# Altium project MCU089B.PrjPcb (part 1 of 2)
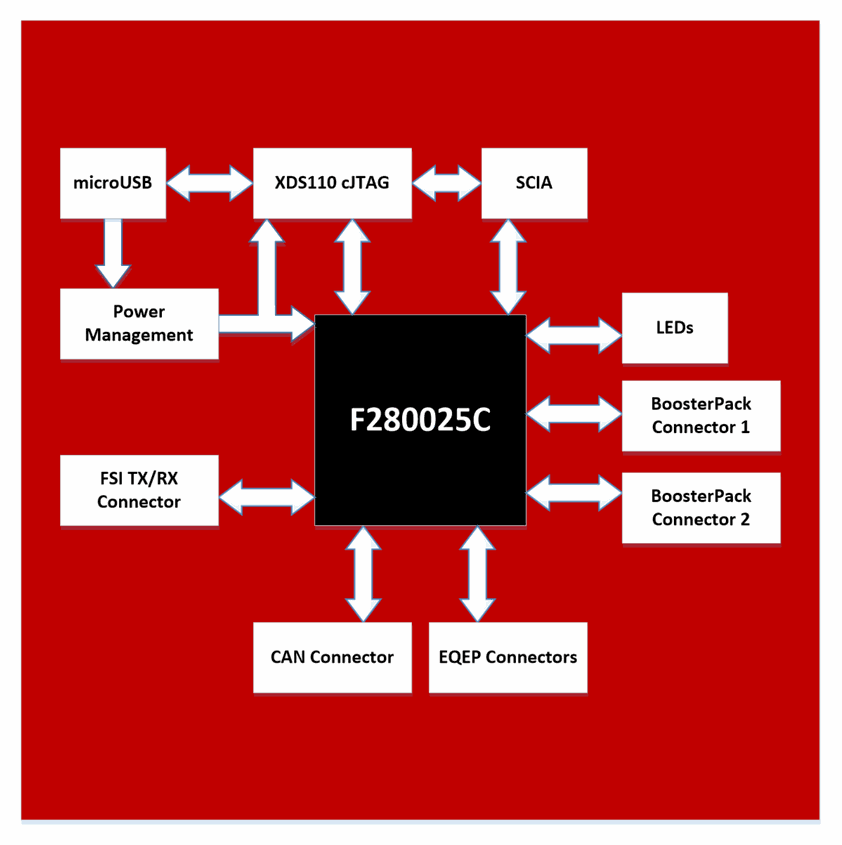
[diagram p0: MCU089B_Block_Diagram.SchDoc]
TID: N/A; TechSupport: http://www.ti.com/support; SCH_Rev: B; PRJ_Title: LAUNCHXL-F280025C; PRJ_Number: MCU089; PRJ_Engineer: Kevin Allen; PRJ_Customer: Public Release; PCB_Rev: B; PCB_Layout: a0232540; CopyrightYear: 2022
7 sheets, 262 parts. Net scope: global (net labels, ports and power ports of the same name join across sheets).
Board file: MCU089B.PcbDoc
Sheets:
  MCU089B_Block_Diagram.SchDoc
  MCU089B_Connectors.SchDoc
  MCU089B_AltRouting_Misc.SchDoc
  MCU089B_F280025C_Device.SchDoc
  MCU089B_XDS110_USB_Power.SchDoc
  MCU089B_XDS110_MCU.SchDoc
  MCU089B_Hardware.SchDoc

## Sheet MCU089B_Block_Diagram.SchDoc
size 431 x 279 mm; Date: Not shown in title block; ApprovedBy: Not shown in title block; CheckedBy: Not shown in title block; Author: Not shown in title block; CompanyName: Not shown in title block; Engineer: Not shown in title block; Organization: Not shown in title block; Address1: Not shown in title block; Address2: Not shown in title block; Address3: Not shown in title block; Address4: Not shown in title block; DocumentNumber: 1; Revision: Use project parameter SCH_Rev; SheetNumber: 1; SheetTotal: 8; PageSetup: Record=PageOptions¦CenterHorizontal=True¦CenterVertical=True¦PrintScale=1.00¦XCorrection=1.00¦YCorrection=1.00¦PrintKind=0¦BorderSize=5000000¦LeftOffset=0¦BottomOffset=0¦Orientation=2¦PaperLength=1000¦PaperWidth=1000¦Scale=100¦PaperSource=15¦PrintQuality=600¦MediaType=1¦DitherType=10¦PaperKind=Letter¦PrintScaleMode=1

## Sheet MCU089B_Connectors.SchDoc
size 431 x 279 mm; Date: Not shown in title block; ApprovedBy: Not shown in title block; CheckedBy: Not shown in title block; Author: Not shown in title block; CompanyName: Not shown in title block; Engineer: Not shown in title block; Organization: Not shown in title block; Address1: Not shown in title block; Address2: Not shown in title block; Address3: Not shown in title block; Address4: Not shown in title block; DocumentNumber: 2; Revision: Use project parameter SCH_Rev; SheetNumber: 2; SheetTotal: 8; PageSetup: Record=PageOptions¦CenterHorizontal=True¦CenterVertical=True¦PrintScale=1.00¦XCorrection=1.00¦YCorrection=1.00¦PrintKind=0¦BorderSize=5000000¦LeftOffset=0¦BottomOffset=0¦Orientation=2¦PaperLength=1000¦PaperWidth=1000¦Scale=100¦PaperSource=15¦PrintQuality=600¦MediaType=1¦DitherType=10¦PaperKind=Letter¦PrintScaleMode=1
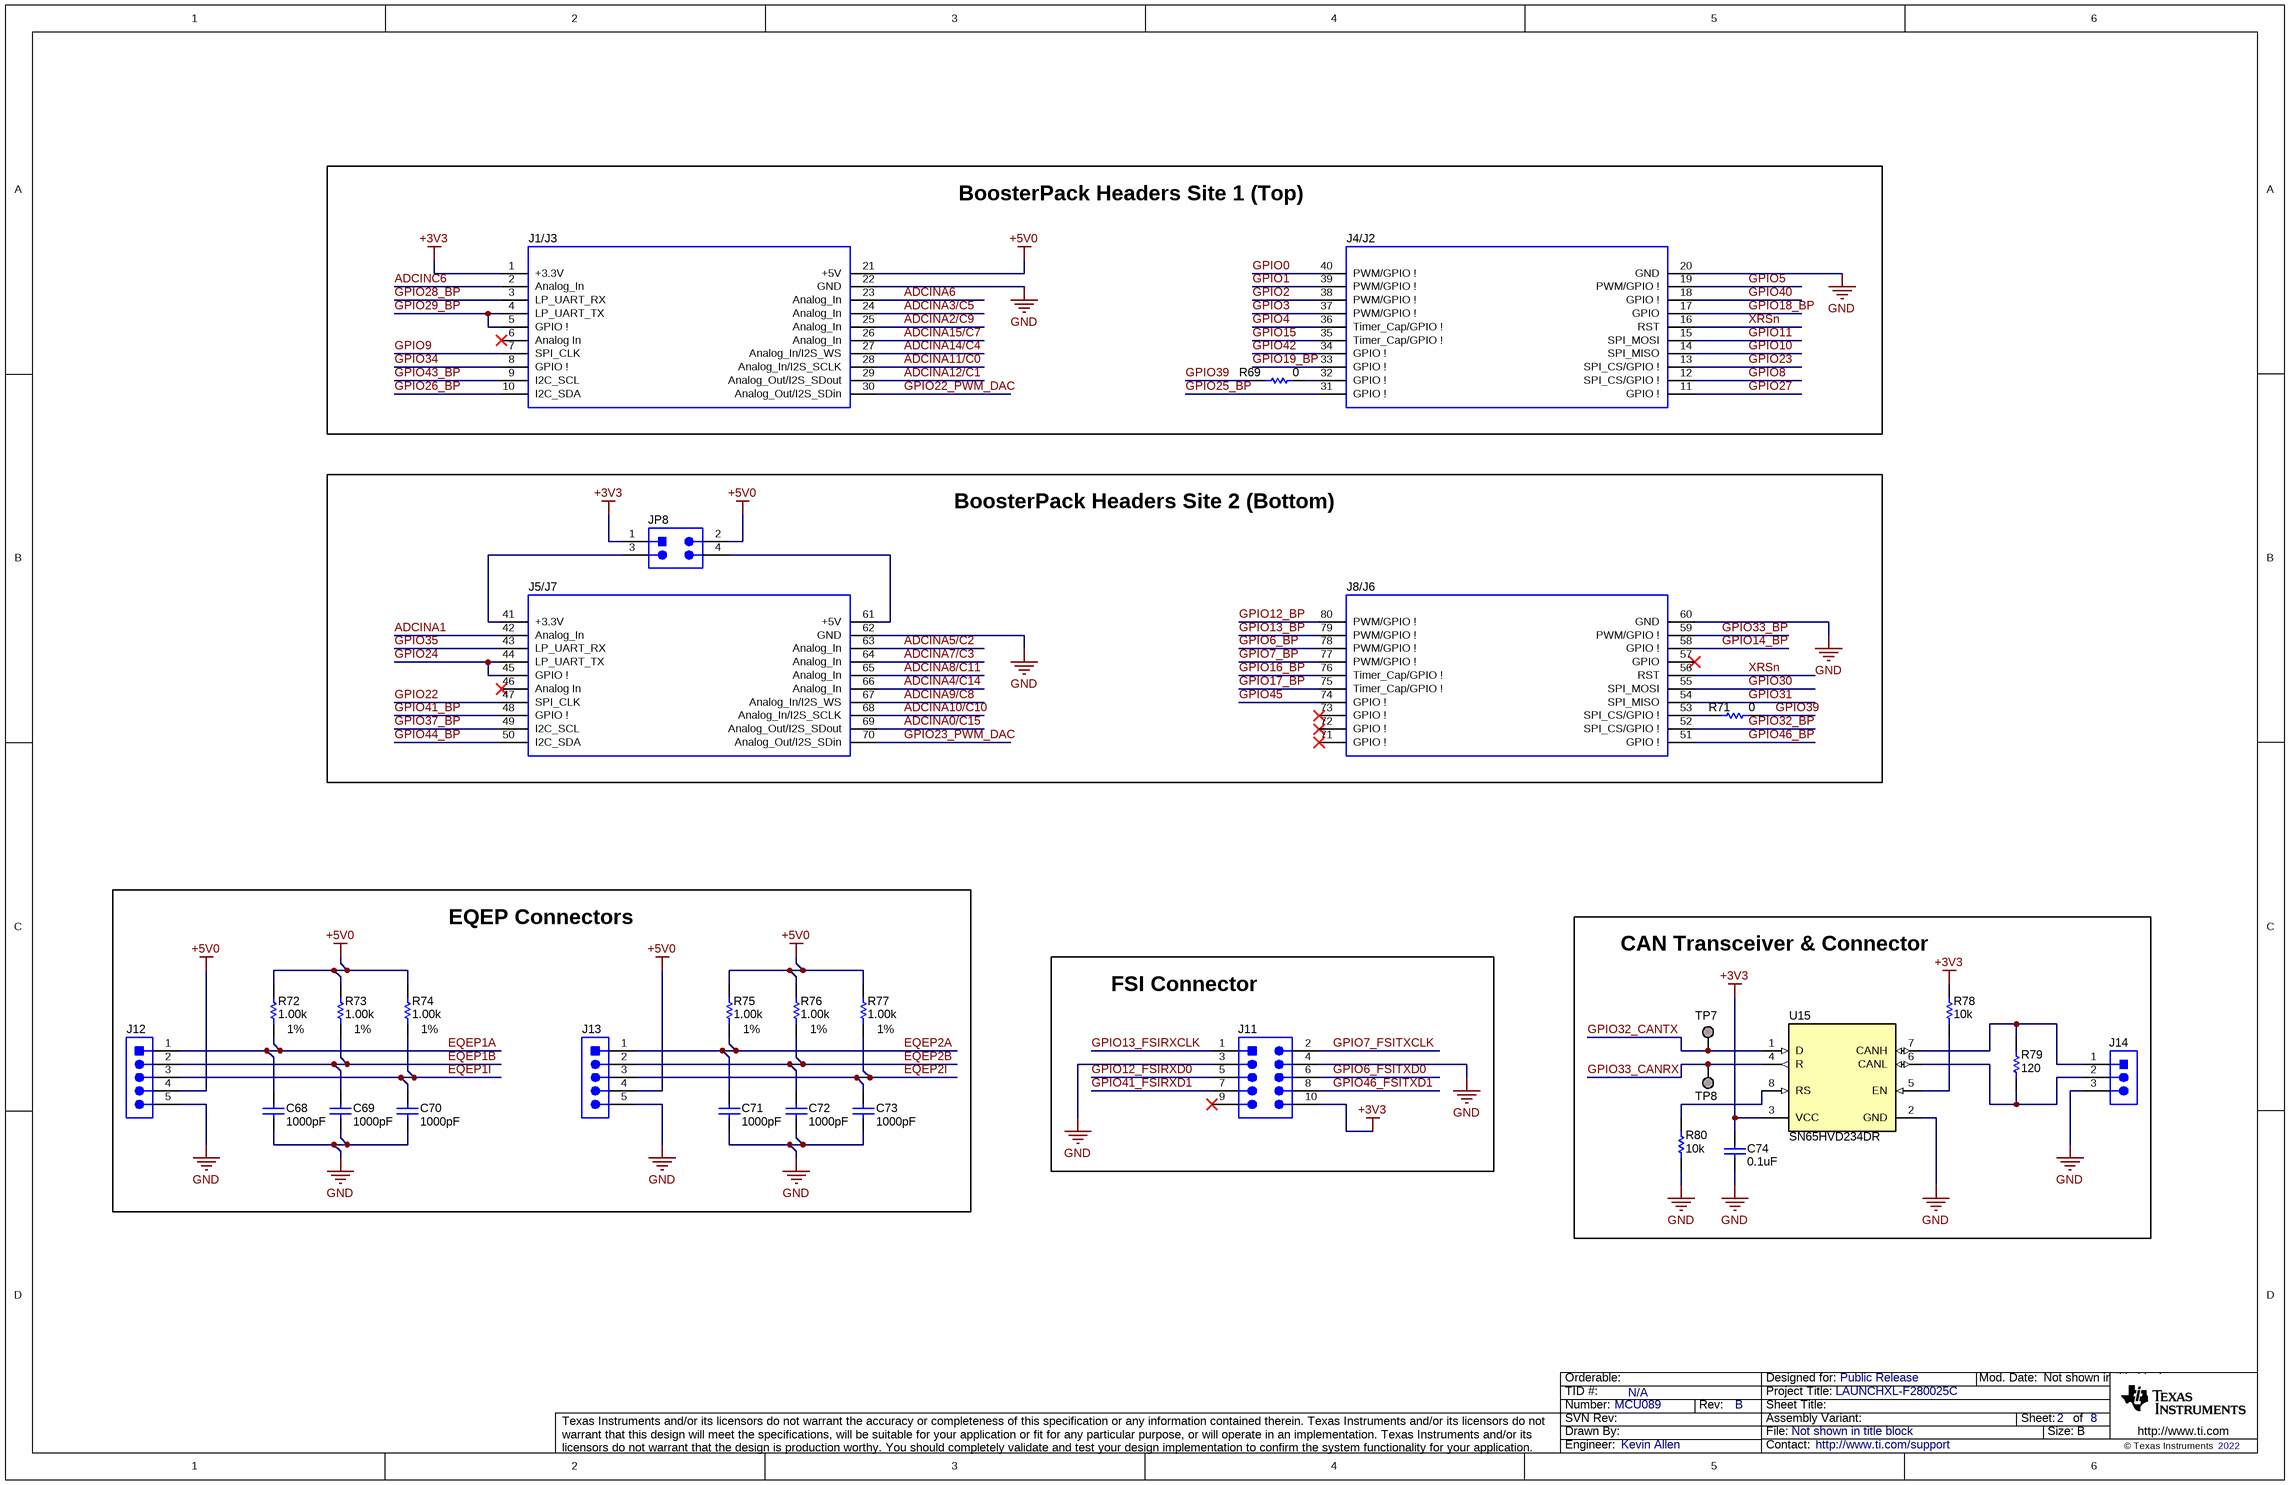
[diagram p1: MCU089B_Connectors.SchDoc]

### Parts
C68  ValueDisplayed: 1000pF  [0402]  (hidden comment: 885012205061)
C69  ValueDisplayed: 1000pF  [0402]  (hidden comment: 885012205061)
C70  ValueDisplayed: 1000pF  [0402]  (hidden comment: 885012205061)
C71  ValueDisplayed: 1000pF  [0402]  (hidden comment: 885012205061)
C72  ValueDisplayed: 1000pF  [0402]  (hidden comment: 885012205061)
C73  ValueDisplayed: 1000pF  [0402]  (hidden comment: 885012205061)
C74  ValueDisplayed: 0.1uF  [0402]  (hidden comment: GRM155R71A104KA01D)
J1/J3  SSQ-110-03-T-D  [BoosterPack_40pin_J1J3]  (value not drawn)
J4/J2  SSQ-110-03-T-D  [BoosterPack_40pin_J2J4]  (value not drawn)
J5/J7  SSQ-110-03-T-D  [BoosterPack_40pin_J5J7]  (value not drawn)
J8/J6  SSQ-110-03-T-D  [BoosterPack_40pin_J6J8]  (value not drawn)
J11  TSW-105-07-G-D  [TSW-105-07-G-D]  (value not drawn)
J12  TSW-105-07-G-S  [TSW-105-07-X-S]  (value not drawn)
J13  TSW-105-07-G-S  [TSW-105-07-X-S]  (value not drawn)
J14  61300311121  [WURTH_61300311121]  (value not drawn)
JP8  TSW-102-07-G-D  [TSW-102-07-G-D]  (value not drawn)
R69  ValueDisplayed: 0  [0603]  (hidden comment: CRCW06030000Z0EA)
R71  ValueDisplayed: 0  [0603]  (hidden comment: CRCW06030000Z0EA)
R72  ValueDisplayed: 1.00k  Value1: 1%  [0402]  (hidden comment: CRCW04021K00FKED)
R73  ValueDisplayed: 1.00k  Value1: 1%  [0402]  (hidden comment: CRCW04021K00FKED)
R74  ValueDisplayed: 1.00k  Value1: 1%  [0402]  (hidden comment: CRCW04021K00FKED)
R75  ValueDisplayed: 1.00k  Value1: 1%  [0402]  (hidden comment: CRCW04021K00FKED)
R76  ValueDisplayed: 1.00k  Value1: 1%  [0402]  (hidden comment: CRCW04021K00FKED)
R77  ValueDisplayed: 1.00k  Value1: 1%  [0402]  (hidden comment: CRCW04021K00FKED)
R78  ValueDisplayed: 10k  [0402]  (hidden comment: CRCW040210K0JNED)
R79  ValueDisplayed: 120  [0603]  (hidden comment: RC0603FR-07120RL)
R80  ValueDisplayed: 10k  [0402]  (hidden comment: CRCW040210K0JNED)
TP7  TESTPOINT  [TP_50MIL-25MILHOLE]  (value not drawn)  (no BOM)
TP8  TESTPOINT  [TP_50MIL-25MILHOLE]  (value not drawn)  (no BOM)
U15  SN65HVD234DR  [D0008A_L]

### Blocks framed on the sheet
BoosterPack Headers Site 1 (Top): J1/J3 J4/J2 R69
BoosterPack Headers Site 2 (Bottom): J5/J7 J8/J6 JP8 R71
EQEP Connectors: C68-C73 J12 J13 R72-R77
FSI Connector: J11
CAN Transceiver & Connector: C74 J14 R78-R80 TP7 TP8 U15

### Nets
+3V3: C74.2 J1/J3.1(+3.3V) J11.10 JP8.1 R78.2 U15.3(VCC)
+5V0: J1/J3.21(+5V) J12.4 J13.4 JP8.2 R72.2 R73.2 R74.2 R75.2 R76.2 R77.2
GND: C68.2 C69.2 C70.2 C71.2 C72.2 C73.2 C74.1 J1/J3.22(GND) J4/J2.20(GND) J5/J7.62(GND) J8/J6.60(GND) J11.3 J11.4 J12.5 J13.5 J14.3 R80.1 U15.2(GND)
ADCINA0/C15: J5/J7.69(Analog_Out/I2S_SDout)
ADCINA1: J5/J7.42(Analog_In)
ADCINA2/C9: J1/J3.25(Analog_In)
ADCINA3/C5: J1/J3.24(Analog_In)
ADCINA4/C14: J5/J7.66(Analog_In)
ADCINA5/C2: J5/J7.63(Analog_In)
ADCINA6: J1/J3.23(Analog_In)
ADCINA7/C3: J5/J7.64(Analog_In)
ADCINA8/C11: J5/J7.65(Analog_In)
ADCINA9/C8: J5/J7.67(Analog_In/I2S_WS)
ADCINA10/C10: J5/J7.68(Analog_In/I2S_SCLK)
ADCINA11/C0: J1/J3.28(Analog_In/I2S_SCLK)
ADCINA12/C1: J1/J3.29(Analog_Out/I2S_SDout)
ADCINA14/C4: J1/J3.27(Analog_In/I2S_WS)
ADCINA15/C7: J1/J3.26(Analog_In)
ADCINC6: J1/J3.2(Analog_In)
EQEP1A: C68.1 J12.1 R72.1
EQEP1B: C69.1 J12.2 R73.1
EQEP1I: C70.1 J12.3 R74.1
EQEP2A: C71.1 J13.1 R75.1
EQEP2B: C72.1 J13.2 R76.1
EQEP2I: C73.1 J13.3 R77.1
GPIO0: J4/J2.40(PWM/GPIO_!)
GPIO1: J4/J2.39(PWM/GPIO_!)
GPIO2: J4/J2.38(PWM/GPIO_!)
GPIO3: J4/J2.37(PWM/GPIO_!)
GPIO4: J4/J2.36(Timer_Cap/GPIO_!)
GPIO5: J4/J2.19(PWM/GPIO_!)
GPIO6_BP: J8/J6.78(PWM/GPIO_!)
GPIO6_FSITXD0: J11.6
GPIO7_BP: J8/J6.77(PWM/GPIO_!)
GPIO7_FSITXCLK: J11.2
GPIO8: J4/J2.12(SPI_CS/GPIO_!)
GPIO9: J1/J3.7(SPI_CLK)
GPIO10: J4/J2.14(SPI_MISO)
GPIO11: J4/J2.15(SPI_MOSI)
GPIO12_BP: J8/J6.80(PWM/GPIO_!)
GPIO12_FSIRXD0: J11.5
GPIO13_BP: J8/J6.79(PWM/GPIO_!)
GPIO13_FSIRXCLK: J11.1
GPIO14_BP: J8/J6.58(GPIO_!)
GPIO15: J4/J2.35(Timer_Cap/GPIO_!)
GPIO16_BP: J8/J6.76(Timer_Cap/GPIO_!)
GPIO17_BP: J8/J6.75(Timer_Cap/GPIO_!)
GPIO18_BP: J4/J2.17(GPIO)
GPIO19_BP: J4/J2.33(GPIO_!)
GPIO22: J5/J7.47(SPI_CLK)
GPIO22_PWM_DAC: J1/J3.30(Analog_Out/I2S_SDin)
GPIO23: J4/J2.13(SPI_CS/GPIO_!)
GPIO23_PWM_DAC: J5/J7.70(Analog_Out/I2S_SDin)
GPIO24: J5/J7.44(LP_UART_TX) J5/J7.45(GPIO_!)
GPIO25_BP: J4/J2.31(GPIO_!)
GPIO26_BP: J1/J3.10(I2C_SDA)
GPIO27: J4/J2.11(GPIO_!)
GPIO28_BP: J1/J3.3(LP_UART_RX)
GPIO29_BP: J1/J3.4(LP_UART_TX) J1/J3.5(GPIO_!)
GPIO30: J8/J6.55(SPI_MOSI)
GPIO31: J8/J6.54(SPI_MISO)
GPIO32_BP: J8/J6.52(SPI_CS/GPIO_!)
GPIO32_CANTX: TP7.1 U15.1(D)
GPIO33_BP: J8/J6.59(PWM/GPIO_!)
GPIO33_CANRX: TP8.1 U15.4(R)
GPIO34: J1/J3.8(GPIO_!)
GPIO35: J5/J7.43(LP_UART_RX)
GPIO37_BP: J5/J7.49(I2C_SCL)
GPIO39: R69.1 R71.2
GPIO40: J4/J2.18(GPIO_!)
GPIO41_BP: J5/J7.48(GPIO_!)
GPIO41_FSIRXD1: J11.7
GPIO42: J4/J2.34(GPIO_!)
GPIO43_BP: J1/J3.9(I2C_SCL)
GPIO44_BP: J5/J7.50(I2C_SDA)
GPIO45: J8/J6.74(GPIO_!)
GPIO46_BP: J8/J6.51(GPIO_!)
GPIO46_FSITXD1: J11.8
XRSn: J4/J2.16(RST) J8/J6.56(RST)
NetJ4/J2_32: J4/J2.32(GPIO_!) R69.2
NetJ5/J7_41: J5/J7.41(+3.3V) JP8.3
NetJ5/J7_61: J5/J7.61(+5V) JP8.4
NetJ8/J6_53: J8/J6.53(SPI_CS/GPIO_!) R71.1
NetJ14_1: J14.1 R79.2 U15.7(CANH)
NetJ14_2: J14.2 R79.1 U15.6(CANL)
NetR78_1: R78.1 U15.5(EN)
NetR80_2: R80.2 U15.8(RS)

Not connected (* = marked no-connect by the designer): J1/J3 6(Analog_In)*; J5/J7 46(Analog_In)*; J8/J6 57(GPIO)* 71(GPIO_!)* 72(GPIO_!)* 73(GPIO_!)*; J11 9*

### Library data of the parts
C68-C73 = CMP-0006231-2: CAP, CERM, 1000 pF, 50 V, +/- 10%, X7R, 0402; Manufacturer: Wurth Elektronik; Polarized: N; Value: 1000pF; U/M: EA; Cap_F: 1nF; Value1: Unknown; VDC_V: 50V; TaMin_C: -55°C; TaMax_C: 125°C; SizeArea_mm2: 0.5; SizeAreaWB_mm2: 3; SizeX_mm: 1; SizeZ_mm: 0.6; AEC Category: Q200
C74 = CMP-0006629-2: CAP, CERM, 0.1 uF, 10 V, +/- 10%, X7R, 0402; Manufacturer: MuRata; Polarized: N; Value: 0.1uF; U/M: EA; Cap_F: 100nF; Value1: Unknown; VDC_V: 10V; TaMin_C: -55°C; TaMax_C: 125°C; SizeArea_mm2: 0.5; SizeAreaWB_mm2: 3; SizeX_mm: 1; SizeZ_mm: 0.6; AEC Category: Q200
J1/J3 = CMP-0003837-4: Receptacle, 2.54mm, 10x2, Tin, TH; Alternate PartNumber: CRD-081413-A-G; Manufacturer: Samtec; Alternate Manufacturer: Major League Electronics; Note: Booster Pack 40 pin J1 and J3; Green_Lifecycle: Active; Green_REACh: Incomplete
J4/J2 = CMP-0078266-4: Receptacle, 2.54mm, 10x2, Tin, TH; Alternate PartNumber: CRD-081413-A-G; Manufacturer: Samtec; Alternate Manufacturer: Major League Electronics; Note: Booster Pack 40 pin J2 and J4; Green_REACh: Incomplete; Green_Lifecycle: Active
J5/J7 = CMP-0081070-3: Receptacle, 2.54mm, 10x2, Tin, TH; Alternate PartNumber: CRD-081413-A-G; Manufacturer: Samtec; Alternate Manufacturer: Major League Electronics; Note: Booster Pack 40 pin J5 and J7; Green_REACh: Incomplete; Green_Lifecycle: Active
J8/J6 = CMP-0081071-3: Receptacle, 2.54mm, 10x2, Tin, TH; Alternate PartNumber: CRD-081413-A-G; Manufacturer: Samtec; Alternate Manufacturer: Major League Electronics; Note: Booster Pack 40 pin J6 and J8; Green_REACh: Incomplete; Green_Lifecycle: Active
J11 = CMP-0075410-2: Header, 100mil, 5x2, Gold, TH; Manufacturer: Samtec; Pitch_mm: 2.54; Cert_VDE: N; Gender: Male; Cert_CSA: Y; Voltage_V: 550V; Green_REACh: Passed; Current_A: 6.3A; Green_Lifecycle: Active; Row_Count: 2
J12 J13 = CMP-0075411-1: Header, 100mil, 5x1, Gold, TH; Manufacturer: Samtec; Pitch_mm: 2.54; Cert_VDE: N; Gender: Male; Cert_CSA: Y; Voltage_V: 550V; Green_REACh: Passed; Current_A: 6.3A; CT: False; Green_Lifecycle: Active; Row_Count: 1; CNHeader: True
J14 = CMP-0054796-1: Header, 2.54 mm, 3x1, Gold, TH; Manufacturer: Wurth Elektronik; Green_Lifecycle: Active; Green_REACh: Passed; CNHeader: TRUE; CT: FALSE
JP8 = CMP-0075404-1: Header, 100mil, 2x2, Gold, TH; Manufacturer: Samtec; CNHeader: True; Shrouded: N; Gender: Male; Row_Count: 2; RowSpacing_mm: 2.54; CT: False; Cert_CSA: Y; Current_A: 6.3A; Green_Lifecycle: Active; Green_REACh: Passed; Voltage_V: 550V
R69 R71 = CMP-0025697-4: RES, 0, 5%, 0.1 W, AEC-Q200 Grade 0, 0603; Manufacturer: Vishay-Dale; Value: 0; Value_Code: 0000; Power_W: 100mW; Value2: 0.1W; VDC_V: 75V; TempCo: 200 ppm/C; SizeArea_mm2: 1.28; SizeX_mm: 1.6; SizeY_mm: 0.8; SizeZ_mm: 1; EIA_Code: E24; AEC Category: Q200; AEC Qualified: Y
R72-R77 = CMP-0026071-3: RES, 1.00 k, 1%, 0.063 W, AEC-Q200 Grade 0, 0402; Manufacturer: Vishay-Dale; Value: 1.00k; Res_ohm: 1k; Value_Code: 1k00; Power_W: 63mW; Value2: 0.063W; VDC_V: 50V; TempCo: 100 ppm/C; SizeArea_mm2: 0.5; SizeX_mm: 1; SizeZ_mm: 0.6; EIA_Code: E96; AEC Category: Q200; AEC Qualified: Y; AEC Grade: 0
R78 R80 = CMP-0026825-5: RES, 10 k, 5%, 0.063 W, AEC-Q200 Grade 0, 0402; Manufacturer: Vishay-Dale; Value: 10k; Value_Code: 10k0; Power_W: 63mW; Value2: 0.063W; VDC_V: 50V; TempCo: 200 ppm/C; SizeArea_mm2: 0.5; SizeX_mm: 1; SizeZ_mm: 0.6; EIA_Code: E24; AEC Category: Q200; AEC Qualified: Y; AEC Grade: 0
R79 = CMP-0022769-3: RES, 120, 1%, 0.1 W, 0603; Manufacturer: Yageo America; Value: 120; Value_Code: 120R; Power_W: 100mW; Value2: 0.1W; VDC_V: 150V; TempCo: 200 ppm/C; SizeArea_mm2: 1.28; SizeX_mm: 1.6; SizeY_mm: 0.8; SizeZ_mm: 1; U/M: EA; AEC Category: Q200
TP7 TP8 = CMP-0078143-3: TEST POINT.  No entry in BOM.
U15 = CMP-0033355-1: 3.3V CAN Transceiver with Sleep Mode, 6 mA, -40 to 125 degC, 8-pin SOIC (D), Green (RoHS & no Sb/Br); Manufacturer: Texas Instruments; Drivers Per Package: 1; Bus Fault Voltage(V): +/-30; Transient Pulse Protection(V): -100 to 100; ICC(Max)(mA): 6; Supply Voltage(s)(V): 3.3; Rating: Catalog

## Sheet MCU089B_AltRouting_Misc.SchDoc
size 431 x 279 mm; Date: Not shown in title block; ApprovedBy: Not shown in title block; CheckedBy: Not shown in title block; Author: Not shown in title block; CompanyName: Not shown in title block; Engineer: Not shown in title block; Organization: Not shown in title block; Address1: Not shown in title block; Address2: Not shown in title block; Address3: Not shown in title block; Address4: Not shown in title block; DocumentNumber: 3; Revision: Use project parameter SCH_Rev; SheetNumber: 3; SheetTotal: 8; PageSetup: Record=PageOptions¦CenterHorizontal=True¦CenterVertical=True¦PrintScale=1.00¦XCorrection=1.00¦YCorrection=1.00¦PrintKind=0¦BorderSize=5000000¦LeftOffset=0¦BottomOffset=0¦Orientation=2¦PaperLength=1000¦PaperWidth=1000¦Scale=100¦PaperSource=15¦PrintQuality=600¦MediaType=1¦DitherType=10¦PaperKind=Letter¦PrintScaleMode=1
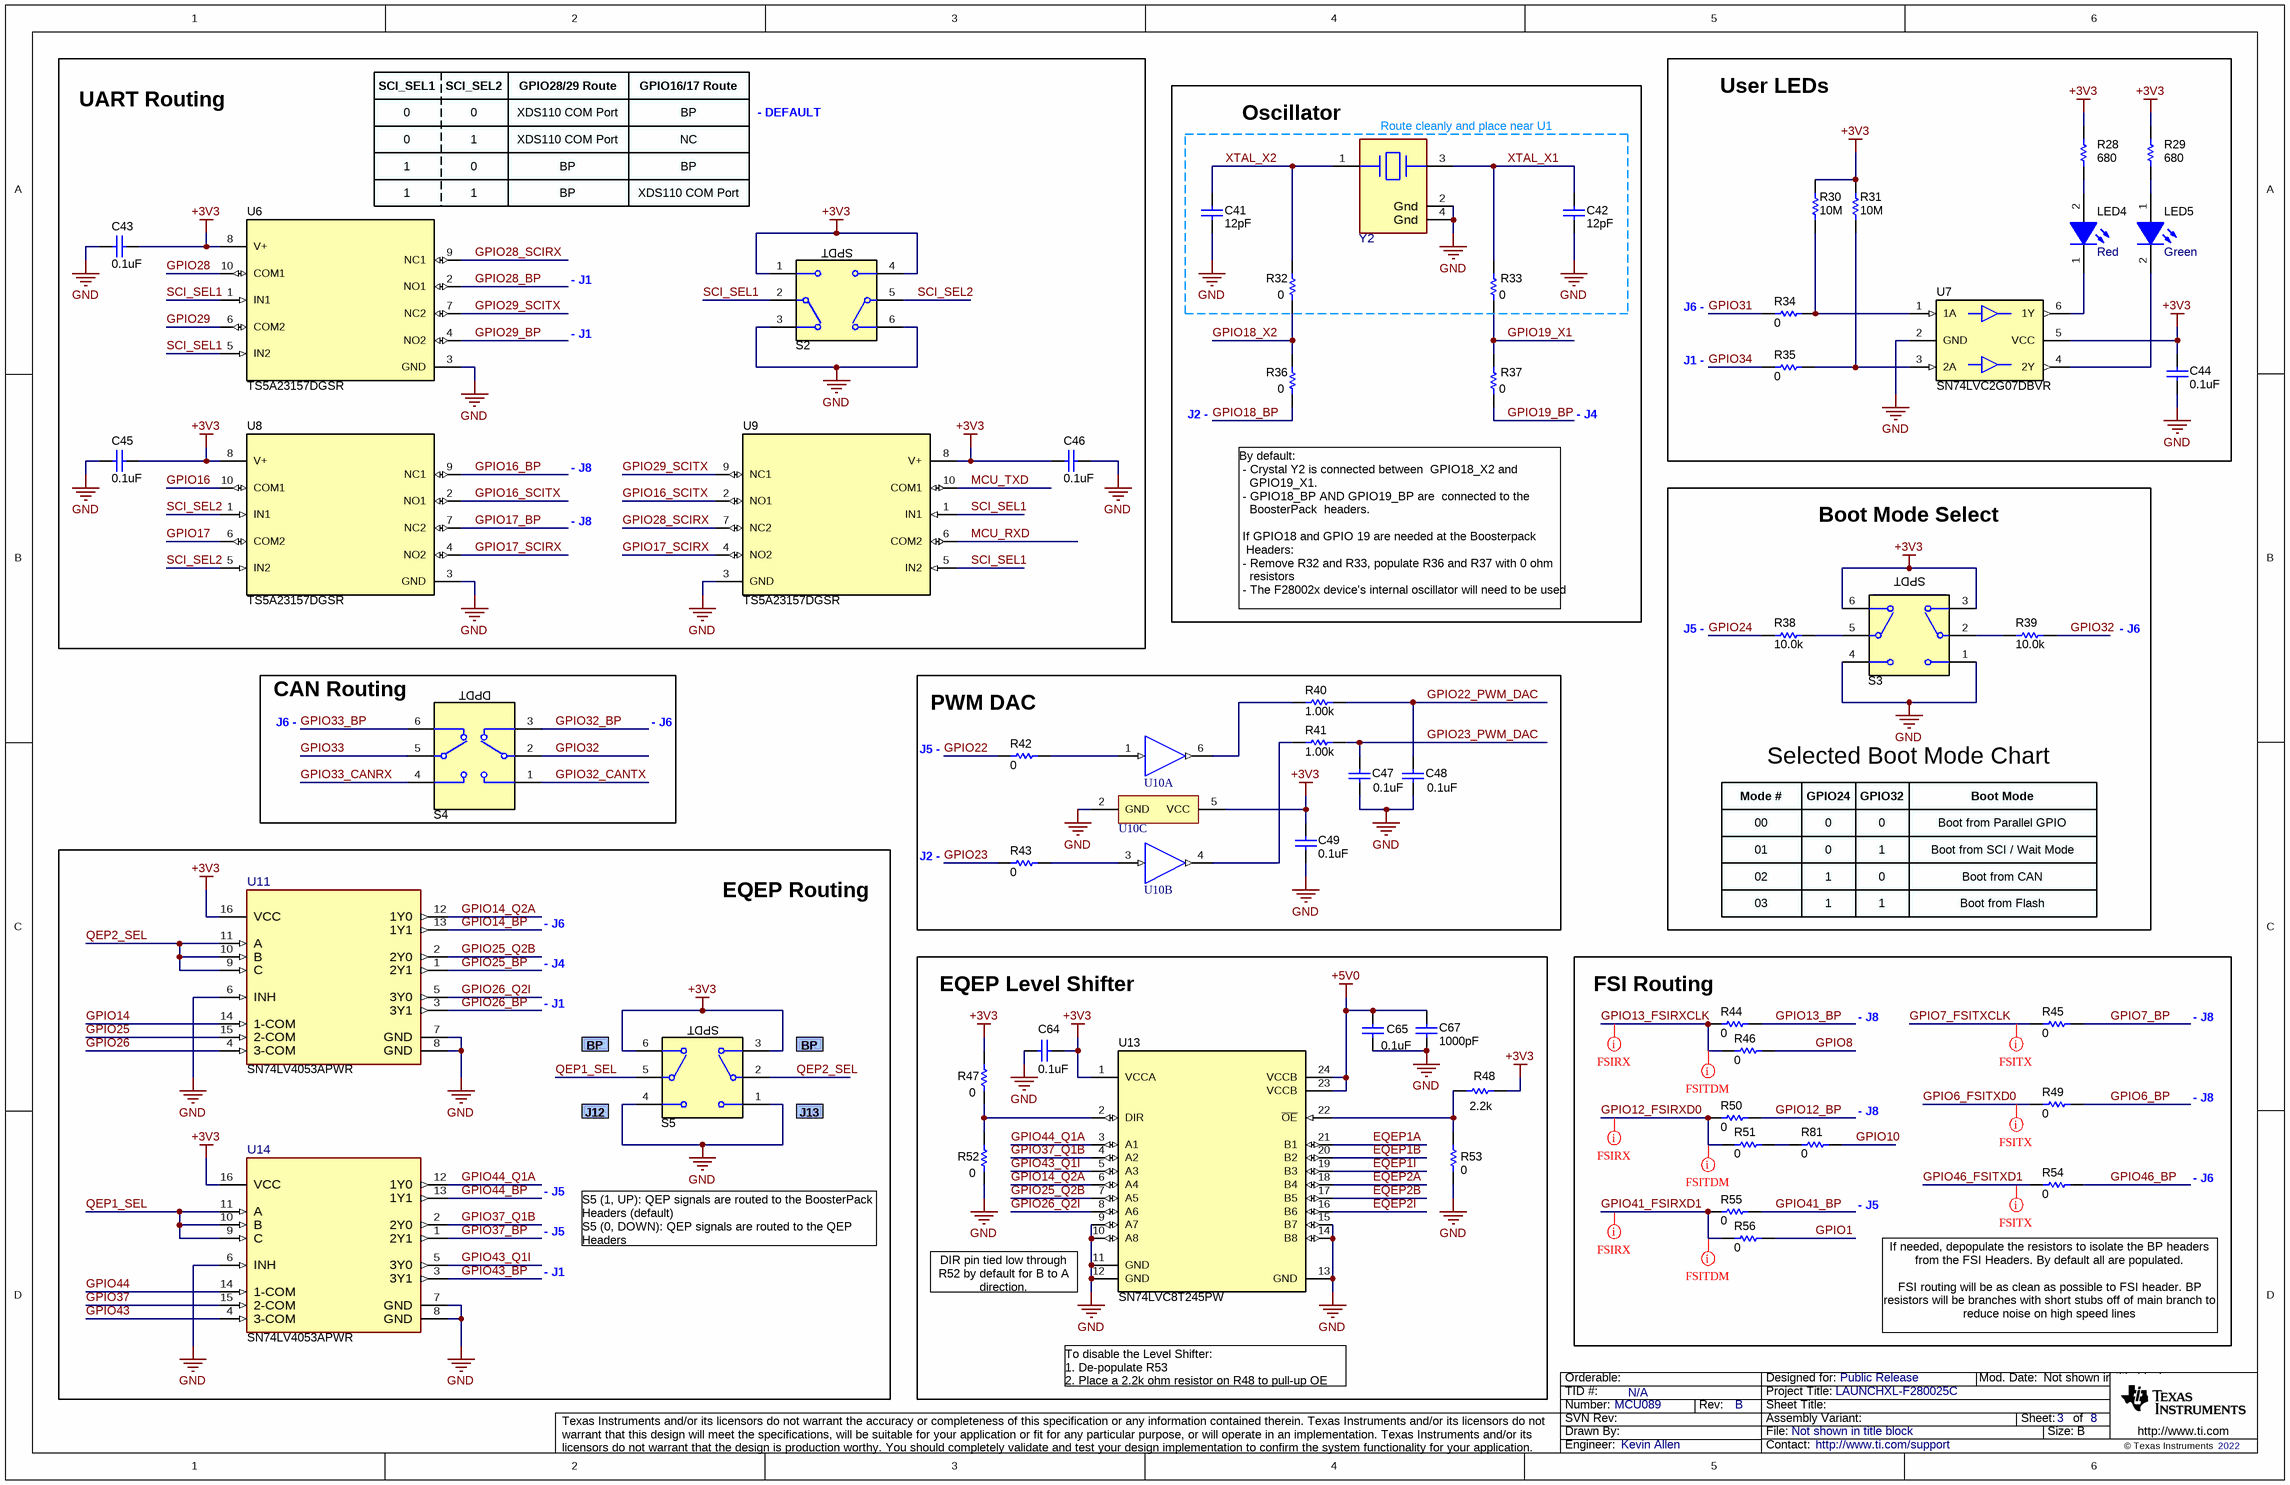
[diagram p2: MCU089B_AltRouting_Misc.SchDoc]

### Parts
C41  ValueDisplayed: 12pF  [0402]  (hidden comment: C0402C120J3GACAUTO)
C42  ValueDisplayed: 12pF  [0402]  (hidden comment: C0402C120J3GACAUTO)
C43  ValueDisplayed: 0.1uF  [0402]  (hidden comment: GRM155R71A104KA01D)
C44  ValueDisplayed: 0.1uF  [0402]  (hidden comment: GRM155R71A104KA01D)
C45  ValueDisplayed: 0.1uF  [0402]  (hidden comment: GRM155R71A104KA01D)
C46  ValueDisplayed: 0.1uF  [0402]  (hidden comment: GRM155R71A104KA01D)
C47  ValueDisplayed: 0.1uF  [0402]  (hidden comment: TMK105B7104MV-FR)
C48  ValueDisplayed: 0.1uF  [0402]  (hidden comment: TMK105B7104MV-FR)
C49  ValueDisplayed: 0.1uF  [0402]  (hidden comment: GRM155R71A104KA01D)
C64  ValueDisplayed: 0.1uF  [0402]  (hidden comment: GRM155R71A104KA01D)
C65  ValueDisplayed: 0.1uF  [0402]  (hidden comment: GRM155R71A104KA01D)
C67  ValueDisplayed: 1000pF  [0402]  (hidden comment: 885012205061)
LED4  value Red  [WL-SMCW_RED_0805]  (hidden comment: 150080SS75000)
LED5  value Green  [LED_LTST-C171]  (hidden comment: LTST-C171GKT)
R28  ValueDisplayed: 680  [0402]  (hidden comment: CRCW0402680RJNED)
R29  ValueDisplayed: 680  [0402]  (hidden comment: CRCW0402680RJNED)
R30  ValueDisplayed: 10M  [0402]  (hidden comment: CRCW040210M0JNED)
R31  ValueDisplayed: 10M  [0402]  (hidden comment: CRCW040210M0JNED)
R32  ValueDisplayed: 0  [0603]  (hidden comment: CRCW06030000Z0EA)
R33  ValueDisplayed: 0  [0603]  (hidden comment: CRCW06030000Z0EA)
R34  ValueDisplayed: 0  [0603]  (hidden comment: CRCW06030000Z0EA)
R35  ValueDisplayed: 0  [0603]  (hidden comment: CRCW06030000Z0EA)
R36  ValueDisplayed: 0  [0603]  (hidden comment: CRCW06030000Z0EA)
R37  ValueDisplayed: 0  [0603]  (hidden comment: CRCW06030000Z0EA)
R38  ValueDisplayed: 10.0k  [0603]  (hidden comment: RC0603FR-0710KL)
R39  ValueDisplayed: 10.0k  [0603]  (hidden comment: RC0603FR-0710KL)
R40  ValueDisplayed: 1.00k  [0402]  (hidden comment: CRCW04021K00FKED)
R41  ValueDisplayed: 1.00k  [0402]  (hidden comment: CRCW04021K00FKED)
R42  ValueDisplayed: 0  [0603]  (hidden comment: CRCW06030000Z0EA)
R43  ValueDisplayed: 0  [0603]  (hidden comment: CRCW06030000Z0EA)
R44  ValueDisplayed: 0  [0603]  (hidden comment: CRCW06030000Z0EA)
R45  ValueDisplayed: 0  [0603]  (hidden comment: CRCW06030000Z0EA)
R46  ValueDisplayed: 0  [0603]  (hidden comment: CRCW06030000Z0EA)
R47  ValueDisplayed: 0  [0603]  (hidden comment: CRCW06030000Z0EA)
R48  ValueDisplayed: 2.2k  [0603]  (hidden comment: CRCW06032K20JNEA)
R49  ValueDisplayed: 0  [0603]  (hidden comment: CRCW06030000Z0EA)
R50  ValueDisplayed: 0  [0603]  (hidden comment: CRCW06030000Z0EA)
R51  ValueDisplayed: 0  [0603]  (hidden comment: CRCW06030000Z0EA)
R52  ValueDisplayed: 0  [0603]  (hidden comment: CRCW06030000Z0EA)
R53  ValueDisplayed: 0  [0603]  (hidden comment: CRCW06030000Z0EA)
R54  ValueDisplayed: 0  [0603]  (hidden comment: CRCW06030000Z0EA)
R55  ValueDisplayed: 0  [0603]  (hidden comment: CRCW06030000Z0EA)
R56  ValueDisplayed: 0  [0603]  (hidden comment: CRCW06030000Z0EA)
R81  ValueDisplayed: 0  [0603]  (hidden comment: CRCW06030000Z0EA)
S2  CAS-D20TA  [SW_CAS-D20TA]  (value not drawn)
S3  CAS-D20TA  [SW_CAS-D20TA]  (value not drawn)
S4  CAS-220TA  [SW_CAS-220TA]  (value not drawn)
S5  CAS-D20TA  [SW_CAS-D20TA]  (value not drawn)
U6  TS5A23157DGSR  [DGS0010A_N]
U7  SN74LVC2G07DBVR  [DBV0006A_N]
U8  TS5A23157DGSR  [DGS0010A_N]
U9  TS5A23157DGSR  [DGS0010A_N]
U10  SN74LVC2G34DBVR  [DBV0006A_N]  (value not drawn)  (parts A,B,C of 3)
U11  SN74LV4053APWR  [PW0016A-MFG]
U13  SN74LVC8T245PW  [PW0024A_N]
U14  SN74LV4053APWR  [PW0016A-MFG]
Y2  ECS-200-8-30B-CKM  [FP-ECS-200-8-30B-CKM_SMD4-MFG]  (value not drawn)

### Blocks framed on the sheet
UART Routing: C43 C45 C46 S2 U6 U8 U9
Oscillator: C41 C42 R32 R33 R36 R37 Y2
User LEDs: C44 LED4 LED5 R28-R31 R34 R35 U7
Selected Boot Mode Chart: R38 R39 S3
CAN Routing: S4
PWM DAC: C47-C49 R40-R43 U10
EQEP Routing: S5 U11 U14
EQEP Level Shifter: C64 C65 C67 R47 R48 R52 R53 U13
FSI Routing: R44-R46 R49-R51 R54-R56 R81

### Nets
+3V3: C43.1 C44.2 C45.1 C46.2 C49.2 C64.1 R28.2 R29.2 R30.2 R31.2 R47.2 R48.2 S2.1 S2.4 S3.3 S3.6 S5.3 S5.6 U6.8(V+) U7.5(VCC) U8.8(V+) U9.8(V+) U10.5(VCC) U11.16(VCC) U13.1(VCCA) U14.16(VCC)
+5V0: C65.2 C67.1 U13.23(VCCB) U13.24(VCCB)
GND: C41.2 C42.2 C43.2 C44.1 C45.2 C46.1 C47.2 C48.2 C49.1 C64.2 C65.1 C67.2 R52.1 R53.2 S2.3 S2.6 S3.1 S3.4 S5.1 S5.4 U6.3(GND) U7.2(GND) U8.3(GND) U9.3(GND) U10.2(GND) U11.6(INH) U11.7(GND) U11.8(GND) U13.9(A7) U13.10(A8) U13.11(GND) U13.12(GND) U13.13(GND) U13.14(B8) U13.15(B7) U14.6(INH) U14.7(GND) U14.8(GND) Y2.2(Gnd) Y2.4(Gnd)
EQEP1A: U13.21(B1)
EQEP1B: U13.20(B2)
EQEP1I: U13.19(B3)
EQEP2A: U13.18(B4)
EQEP2B: U13.17(B5)
EQEP2I: U13.16(B6)
GPIO1: R56.2
GPIO6_BP: R49.2
GPIO6_FSITXD0: R49.1
GPIO7_BP: R45.2
GPIO7_FSITXCLK: R45.1
GPIO8: R46.2
GPIO10: R81.2
GPIO12_BP: R50.2
GPIO12_FSIRXD0: R50.1 R51.1
GPIO13_BP: R44.2
GPIO13_FSIRXCLK: R44.1 R46.1
GPIO14: U11.14(1-COM)
GPIO14_BP: U11.13(1Y1)
GPIO14_Q2A: U11.12(1Y0) U13.6(A4)
GPIO16: U8.10(COM1)
GPIO16_BP: U8.9(NC1)
GPIO16_SCITX: U8.2(NO1) U9.2(NO1)
GPIO17: U8.6(COM2)
GPIO17_BP: U8.7(NC2)
GPIO17_SCIRX: U8.4(NO2) U9.4(NO2)
GPIO18_BP: R36.1
GPIO18_X2: R32.1 R36.2
GPIO19_BP: R37.1
GPIO19_X1: R33.1 R37.2
GPIO22: R42.1
GPIO22_PWM_DAC: C48.1 R40.2
GPIO23: R43.1
GPIO23_PWM_DAC: C47.1 R41.2
GPIO24: R38.1
GPIO25: U11.15(2-COM)
GPIO25_BP: U11.1(2Y1)
GPIO25_Q2B: U11.2(2Y0) U13.7(A5)
GPIO26: U11.4(3-COM)
GPIO26_BP: U11.3(3Y1)
GPIO26_Q2I: U11.5(3Y0) U13.8(A6)
GPIO28: U6.10(COM1)
GPIO28_BP: U6.2(NO1)
GPIO28_SCIRX: U6.9(NC1) U9.7(NC2)
GPIO29: U6.6(COM2)
GPIO29_BP: U6.4(NO2)
GPIO29_SCITX: U6.7(NC2) U9.9(NC1)
GPIO31: R34.1
GPIO32: R39.2 S4.2
GPIO32_BP: S4.3
GPIO32_CANTX: S4.1
GPIO33: S4.5
GPIO33_BP: S4.6
GPIO33_CANRX: S4.4
GPIO34: R35.1
GPIO37: U14.15(2-COM)
GPIO37_BP: U14.1(2Y1)
GPIO37_Q1B: U13.4(A2) U14.2(2Y0)
GPIO41_BP: R55.2
GPIO41_FSIRXD1: R55.1 R56.1
GPIO43: U14.4(3-COM)
GPIO43_BP: U14.3(3Y1)
GPIO43_Q1I: U13.5(A3) U14.5(3Y0)
GPIO44: U14.14(1-COM)
GPIO44_BP: U14.13(1Y1)
GPIO44_Q1A: U13.3(A1) U14.12(1Y0)
GPIO46_BP: R54.2
GPIO46_FSITXD1: R54.1
MCU_RXD: U9.6(COM2)
MCU_TXD: U9.10(COM1)
QEP1_SEL: S5.5(C) U14.9(C) U14.10(B) U14.11(A)
QEP2_SEL: S5.2(C) U11.9(C) U11.10(B) U11.11(A)
SCI_SEL1: S2.2(C) U6.1(IN1) U6.5(IN2) U9.1(IN1) U9.5(IN2)
SCI_SEL2: S2.5(C) U8.1(IN1) U8.5(IN2)
XTAL_X1: C42.1 R33.2 Y2.3(Out/In)
XTAL_X2: C41.1 R32.2 Y2.1(In/Out)
NetLED4_1: LED4.1(K) U7.6(1Y)
NetLED4_2: LED4.2(A) R28.1
NetLED5_1: LED5.1(A) R29.1
NetLED5_2: LED5.2(K) U7.4(2Y)
NetR30_1: R30.1 R34.2 U7.1(1A)
NetR31_1: R31.1 R35.2 U7.3(2A)
NetR38_2: R38.2 S3.5(C)
NetR39_1: R39.1 S3.2(C)
NetR40_1: R40.1 U10.6(1Y)
NetR41_1: R41.1 U10.4(2Y)
NetR42_2: R42.2 U10.1(1A)
NetR43_2: R43.2 U10.3(2A)
NetR47_1: R47.1 R52.2 U13.2(DIR)
NetR48_1: R48.1 R53.1 U13.22(~{OE})
NetR51_2: R51.2 R81.1

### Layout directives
net class FSIRX: GPIO12_FSIRXD0, GPIO13_FSIRXCLK, GPIO41_FSIRXD1
net class FSITX: GPIO6_FSITXD0, GPIO7_FSITXCLK, GPIO46_FSITXD1

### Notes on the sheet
- SCI_SEL1
- SCI_SEL2
- GPIO28/29 Route
- GPIO16/17 Route
- 0
- 1
- XDS110 COM Port
- BP
- NC
- - DEFAULT
- (near Y2) Route cleanly and place near U1
- (near U6) 1
- - J1
- (near S2) SPDT
- J6 -
- J1 -
- J2 -
- - J4
- - J8
- Boot Mode Select
- By default:
  - Crystal Y2 is connected between  GPIO18_X2 and
  GPIO19_X1.
  - GPIO18_BP AND GPIO19_BP are  connected to the
  BoosterPack  headers.
  If GPIO18 and GPIO 19 are needed at the Boosterpack
  Headers:
  - Remove R32 and R33, populate R36 and R37 with 0 ohm
  resistors
  - The F28002x device's internal oscillator will need to be used
- J5 -
- (near S3) SPDT
- - J6
- (near S4) DPDT
- Mode #
- 00
- GPIO24
- GPIO32
- Boot Mode
- Boot from Parallel GPIO
- 01
- 02
- 03
- Boot from SCI / Wait Mode
- Boot from CAN
- Boot from Flash
- (near S5) SPDT
- (near R81) - J8
- J12
- J13
- - J5
- S5 (1, UP): QEP signals are routed to the BoosterPack Headers (default)
  S5 (0, DOWN): QEP signals are routed to the QEP Headers
- (near U13) DIR pin tied low through R52 by default for B to A direction.
- If needed, depopulate the resistors to isolate the BP headers from the FSI Headers. By default all are populated.
  FSI routing will be as clean as possible to FSI header. BP resistors will be branches with short stubs off of main branch to reduce noise on high speed lines
- To disable the Level Shifter:
  1. De-populate R53
  2. Place a 2.2k ohm resistor on R48 to pull-up OE

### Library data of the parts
C41 C42 = CMP-0006239-2: CAP, CERM, 12 pF, 25 V, +/- 5%, C0G/NP0, AEC-Q200 Grade 1, 0402; Manufacturer: Kemet; TaMin_C: -55°C; Polarized: N; SizeAreaWB_mm2: 3; Value1: Unknown; U/M: EA; Value: 12pF; TaMax_C: 125°C; SizeZ_mm: 0.6; SizeX_mm: 1; SizeY_mm: 0.5; Value2: 25V; AEC Qualified: Y; AEC Category: Q200
C43-C46 C49 C64 C65 = CMP-0006629-2: as C74 on sheet MCU089B_Connectors
C47 C48 = CMP-0006720-2: CAP, CERM, 0.1 uF, 25 V, +/- 20%, X7R, 0402; Manufacturer: Taiyo Yuden; TaMin_C: -55°C; Polarized: N; SizeAreaWB_mm2: 3; Value1: Unknown; U/M: EA; Value: 0.1uF; TaMax_C: 125°C; SizeZ_mm: 0.6; SizeX_mm: 1; SizeY_mm: 0.5; Value2: 25V; Cap_F: 100nF; AEC Category: Q200
C67 = CMP-0006231-2: as C68 on sheet MCU089B_Connectors
LED4 = CMP-0002951-3: LED, Red, SMD; Manufacturer: Wurth Elektronik; Type: AlInGaP; Vf_V: 1.9V; Io_A: 30mA; Vr_V: 5V; Ir_A: 25µA; Tjmax_C: 85°C; Power_TotalModule: 72mW; Value1: 0.072W; Angle: 140
LED5 = CMP-0002830-3: LED, Green, SMD; Manufacturer: Lite-On; Type: AlInGaP; Vf_V: 2.1V; Io_A: 20A; Value1: W; SizeAreaWB_mm2: 6.75; SizeArea_mm2: 2.5; SizeX_mm: 2; SizeY_mm: 1.25; SizeZ_mm: 1.2
R28 R29 = CMP-0026962-3: RES, 680, 5%, 0.063 W, AEC-Q200 Grade 0, 0402; Manufacturer: Vishay-Dale; Power_W: 63mW; TempCo: 200 ppm/C; Value_Code: 680R; Value: 680; EIA_Code: E24; SizeX_mm: 1; SizeY_mm: 0.5; SizeZ_mm: 0.6; Value2: 0.063W; CompType: Resistor; AEC Qualified: Y; VDC_V: 50V; AEC Category: Q200; AEC Grade: 0
R30 R31 = CMP-0026826-2: RES, 10 M, 5%, 0.063 W, AEC-Q200 Grade 0, 0402; Manufacturer: Vishay-Dale; Value: 10Meg; Value_Code: 10M0; Power_W: 63mW; Value2: 0.063W; VDC_V: 50V; TempCo: 200 ppm/C; SizeArea_mm2: 0.5; SizeX_mm: 1; SizeZ_mm: 0.6; EIA_Code: E24; AEC Category: Q200; AEC Qualified: Y; AEC Grade: 0
R32-R37 R42-R47 R49-R56 R81 = CMP-0025697-4: as R69 on sheet MCU089B_Connectors
R38 R39 = CMP-0022746-5: RES, 10.0 k, 1%, 0.1 W, 0603; Manufacturer: Yageo; Power_W: 100mW; TempCo: 100 ppm/C; Value_Code: 10k0; Value: 10.0k; EIA_Code: E96; Res_ohm: 10k; SizeX_mm: 1.6; SizeY_mm: 0.8; SizeZ_mm: 1; Value2: 0.1W; SizeArea_mm2: 1.28; AEC Qualified: N; VDC_V: 75V; AEC Category: Q200; SizeAreaWB_mm2: 4.68
R40 R41 = CMP-0026071-3: RES, 1.00 k, 1%, 0.063 W, AEC-Q200 Grade 0, 0402; Manufacturer: Vishay-Dale; Power_W: 63mW; TempCo: 100 ppm/C; Value_Code: 1k00; Value: 1.00k; EIA_Code: E96; Res_ohm: 1k; SizeX_mm: 1; SizeY_mm: 0.5; SizeZ_mm: 0.6; Value2: 0.063W; AEC Qualified: Y; VDC_V: 50V; AEC Category: Q200; AEC Grade: 0
R48 = CMP-0025769-4: RES, 2.2 k, 5%, 0.1 W, AEC-Q200 Grade 0, 0603; Manufacturer: Vishay-Dale; Value: 2.2k; Value_Code: 2k20; Power_W: 100mW; Value2: 0.1W; VDC_V: 75V; TempCo: 200 ppm/C; SizeArea_mm2: 1.28; SizeX_mm: 1.6; SizeY_mm: 0.8; SizeZ_mm: 1; EIA_Code: E24; AEC Category: Q200; AEC Qualified: Y; AEC Grade: 0
S2 S5 = CMP-0002233-1: Switch, Dual SPDT,  2 Pos, 0.1A, 6VDC, SMD; Manufacturer: Copal Electronics; VDC_V: 6V; SwitchFunction: On-On; PositionCount: 2; CurrentRating_mA: 100A
S3 = CMP-0002233-1: Switch, Dual SPDT,  2 Pos, 0.1A, 6VDC, SMD; Manufacturer: Copal Electronics; CurrentRating_mA: 100A; SwitchFunction: On-On; VDC_V: 6V; PositionCount: 2
S4 = CMP-0002123-2: SLIDE SWITCH DPDT  .1A, SMT; Manufacturer: Copal Electronics; VDC_V: 6V; SwitchFunction: On-On; PositionCount: 2; CurrentRating_mA: 100A
U6 U8 U9 = CMP-0067418-1: DUAL 10-Ohm SPDT ANALOG SWITCH, DGS0010A (VSSOP-10); Alternate PartNumber: TS5A23157DGST; Alternate Manufacturer: Texas Instruments; Green_Lifecycle: Active; SizeAreaWB_mm2: 23.6; Green_REACh: Passed; U/M: EA; SizeZ_mm: 1.1; SizeX_mm: 4.9; SizeY_mm: 3.0; SizeArea_mm2: 14.7; CompType: IC
U7 = CMP-0051789-2: Dual Buffer/Driver with Open-Drain Output, DBV0006A, LARGE T&R; Manufacturer: Texas Instruments; VCC(Min)(V): 1.65; VCC(Max)(V): 5.5; Output Type: CMOS; ICC @ Nom Voltage(Max)(mA): 0.01; Input Type: CMOS/TTL; Bits(#): 2; F @ Nom Voltage(Max)(Mhz): 150; Rating: Catalog; Technology Family: LVC; Voltage(Nom)(V): 1.8,2.5,3.3,5; Schmitt Trigger: No; Output Drive (IOL/IOH)(Max)(mA): 32/-32; tpd @ Nom Voltage(Max)(ns): 8.6,4.4,3.7,2.9; Logic: True; Sub-Family: Inverting Buffer/Driver; AEC Category: Q200; AEC Qualified: N; CompType: IC; Green_Lifecycle: Active; Green_REACh: Passed; SizeArea_mm2: 8.12; SizeAreaWB_mm2: 14.82; SizeX_mm: 2.8; SizeY_mm: 2.9; SizeZ_mm: 1.45
U10 = CMP-0051910-1: Dual Buffer Gate, DBV0006A, LARGE T&R; Manufacturer: Texas Instruments; Logic: True; F @ Nom Voltage(Max)(Mhz): 150; Output Type: CMOS; Output Drive (IOL/IOH)(Max)(mA): 32/-32; Voltage(Nom)(V): 1.8,2.5,3.3,5; 3-State Output: No; VCC(Max)(V): 5.5; ICC @ Nom Voltage(Max)(mA): 0.01; Technology Family: LVC; Input Type: CMOS/TTL; VCC(Min)(V): 1.65; Bits(#): 2; tpd @ Nom Voltage(Max)(ns): 8.6,4.4,4.1,3.2; Rating: Catalog; Sub-Family: Non-Inverting Buffer/Driver
U11 U14 = CMP-0089841-1: 3 Circuit IC Switch 2:1 75Ohm 16-TSSOP; Manufacturer: Texas Instruments; TaMax_C: +85°C; Max Supply Voltage: 5.5V; PositionCount: 3; AEC Qualified: No; SizeZ_mm: 1.2mm; Standoff Height: 0.05mm; On State Resistance: 100-225Ω; Min Supply Voltage: 2V; -3Db Bandwith: 50MHz; Nominal Supply Current: 20uA; TaMin_C: -40°C
U13 = CMP-0066458-2: 8-Bit Dual-Supply Bus Transceiver with Configurable Voltage-Level Shifting and Three-State Outputs, PW0024A (TSSOP-24); Alternate Manufacturer: Texas Instruments; SizeAreaWB_mm2: 82.32; SizeZ_mm: 1.2; SizeX_mm: 6.4; SizeY_mm: 7.8; SizeArea_mm2: 49.92; CompType: IC; AEC Category: Q200; AEC Qualified: N; Rating: Catalog
Y2 = CMP-0093370-1: 20 MHz ±10ppm Crystal 8pF 40 Ohms 4-SMD, No Lead; Manufacturer: ECS International; Frequency_Fixed: 20MHz; Esr: 40; SizeZ_mm: 0.85mm

## Sheet MCU089B_F280025C_Device.SchDoc
size 431 x 279 mm; Date: Not shown in title block; ApprovedBy: Not shown in title block; CheckedBy: Not shown in title block; Author: Not shown in title block; CompanyName: Not shown in title block; Engineer: Not shown in title block; Organization: Not shown in title block; Address1: Not shown in title block; Address2: Not shown in title block; Address3: Not shown in title block; Address4: Not shown in title block; DocumentNumber: 4; Revision: Use project parameter SCH_Rev; SheetNumber: 4; SheetTotal: 8; PageSetup: Record=PageOptions¦CenterHorizontal=True¦CenterVertical=True¦PrintScale=1.00¦XCorrection=1.00¦YCorrection=1.00¦PrintKind=0¦BorderSize=5000000¦LeftOffset=0¦BottomOffset=0¦Orientation=2¦PaperLength=1000¦PaperWidth=1000¦Scale=100¦PaperSource=15¦PrintQuality=600¦MediaType=1¦DitherType=10¦PaperKind=Letter¦PrintScaleMode=1
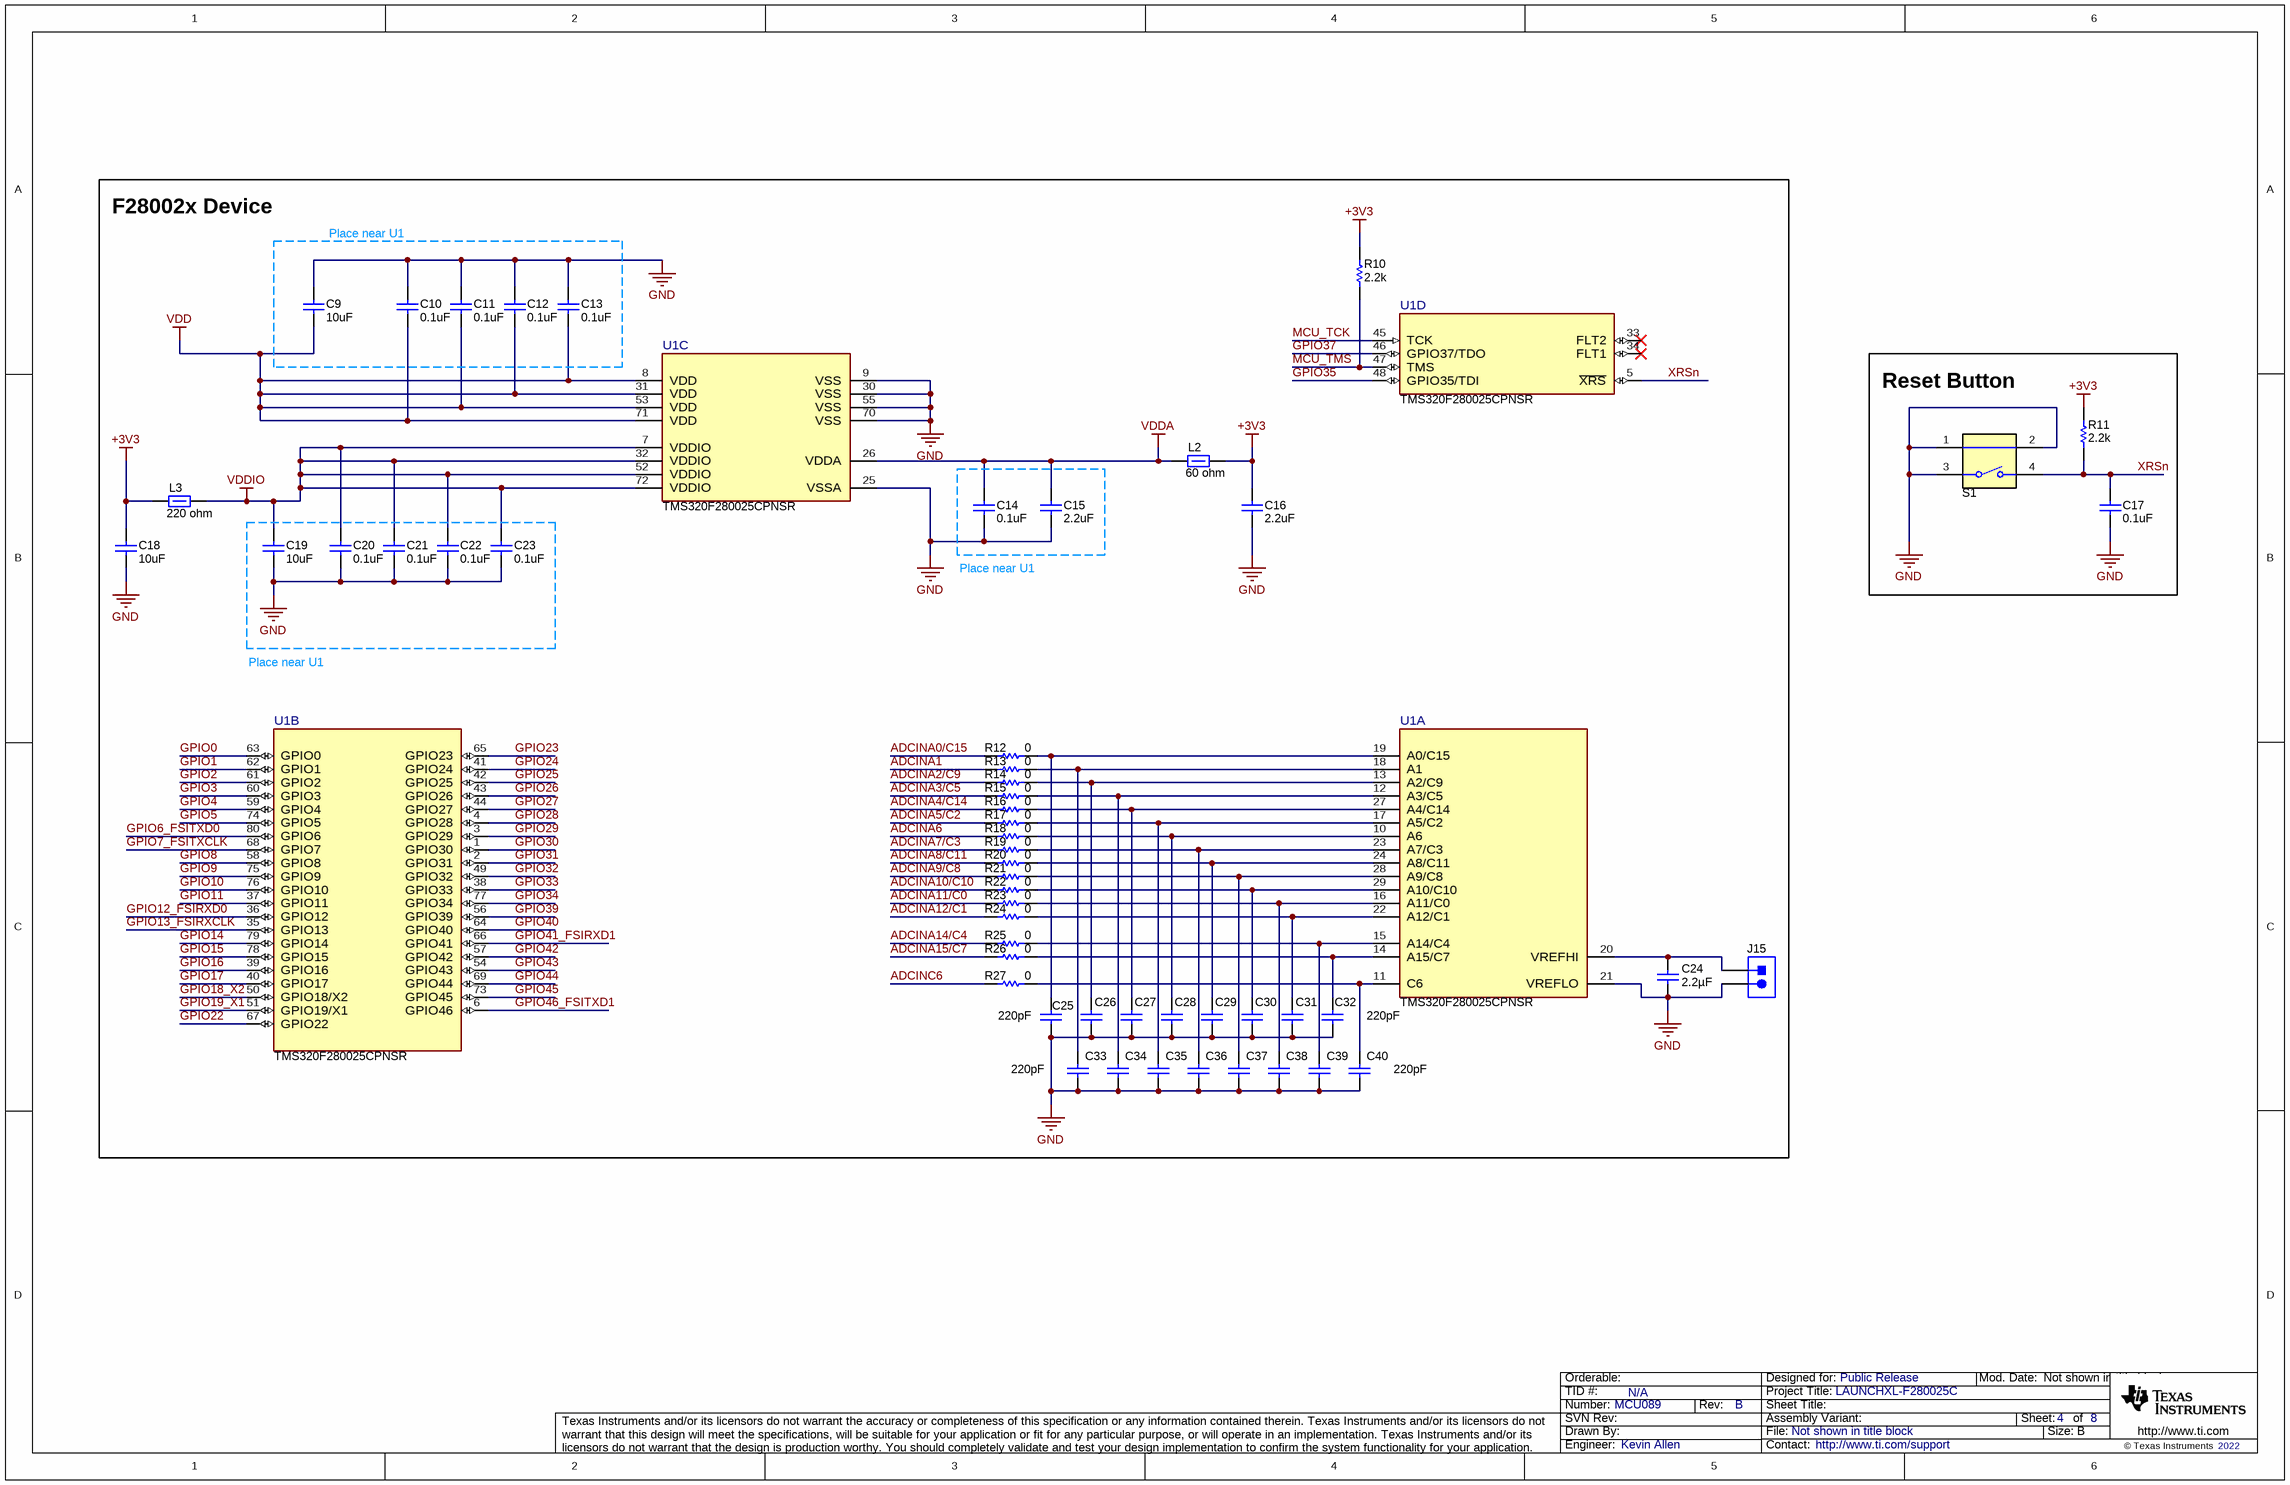
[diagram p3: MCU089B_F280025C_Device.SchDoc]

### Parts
C9  ValueDisplayed: 10uF  [0603]  (hidden comment: GRM188R61A106ME69D)
C10  ValueDisplayed: 0.1uF  [0402]  (hidden comment: GRM155R71A104KA01D)
C11  ValueDisplayed: 0.1uF  [0402]  (hidden comment: GRM155R71A104KA01D)
C12  ValueDisplayed: 0.1uF  [0402]  (hidden comment: GRM155R71A104KA01D)
C13  ValueDisplayed: 0.1uF  [0402]  (hidden comment: GRM155R71A104KA01D)
C14  ValueDisplayed: 0.1uF  [0402]  (hidden comment: GRM155R71A104KA01D)
C15  ValueDisplayed: 2.2uF  [0603]  (hidden comment: GRM188R61A225KE34D)
C16  ValueDisplayed: 2.2uF  [0603]  (hidden comment: GRM188R61A225KE34D)
C17  ValueDisplayed: 0.1uF  [0402]  (hidden comment: GRM155R71A104KA01D)
C18  ValueDisplayed: 10uF  [0603]  (hidden comment: GRM188R61A106ME69D)
C19  ValueDisplayed: 10uF  [0603]  (hidden comment: GRM188R61A106ME69D)
C20  ValueDisplayed: 0.1uF  [0402]  (hidden comment: GRM155R71A104KA01D)
C21  ValueDisplayed: 0.1uF  [0402]  (hidden comment: GRM155R71A104KA01D)
C22  ValueDisplayed: 0.1uF  [0402]  (hidden comment: GRM155R71A104KA01D)
C23  ValueDisplayed: 0.1uF  [0402]  (hidden comment: GRM155R71A104KA01D)
C24  Cap_F: 2.2µF  [0603]  (hidden comment: GRM188R61A225KE34D)
C25  Cap_F: 220pF  [0402]  (hidden comment: C1005C0G1H221F050BA)
C26  C1005C0G1H221F050BA  [0402]  (value not drawn)
C27  C1005C0G1H221F050BA  [0402]  (value not drawn)
C28  C1005C0G1H221F050BA  [0402]  (value not drawn)
C29  C1005C0G1H221F050BA  [0402]  (value not drawn)
C30  C1005C0G1H221F050BA  [0402]  (value not drawn)
C31  C1005C0G1H221F050BA  [0402]  (value not drawn)
C32  Cap_F: 220pF  [0402]  (hidden comment: C1005C0G1H221F050BA)
C33  Cap_F: 220pF  [0402]  (hidden comment: C1005C0G1H221F050BA)
C34  C1005C0G1H221F050BA  [0402]  (value not drawn)
C35  C1005C0G1H221F050BA  [0402]  (value not drawn)
C36  C1005C0G1H221F050BA  [0402]  (value not drawn)
C37  C1005C0G1H221F050BA  [0402]  (value not drawn)
C38  C1005C0G1H221F050BA  [0402]  (value not drawn)
C39  C1005C0G1H221F050BA  [0402]  (value not drawn)
C40  Cap_F: 220pF  [0402]  (hidden comment: C1005C0G1H221F050BA)
J15  61300211121  [WURTH_61300211121]  (value not drawn)
L2  value 60 ohm  [0805_HV]  (hidden comment: 742792063)
L3  ValueDisplayed: 220 ohm  [0805_HV]  (hidden comment: 742792022)
R10  ValueDisplayed: 2.2k  [0402]  (hidden comment: CRCW04022K20JNED)
R11  ValueDisplayed: 2.2k  [0402]  (hidden comment: CRCW04022K20JNED)
R12  ValueDisplayed: 0  [0402]  (hidden comment: ERJ-2GE0R00X)
R13  ValueDisplayed: 0  [0402]  (hidden comment: ERJ-2GE0R00X)
R14  ValueDisplayed: 0  [0402]  (hidden comment: ERJ-2GE0R00X)
R15  ValueDisplayed: 0  [0402]  (hidden comment: ERJ-2GE0R00X)
R16  ValueDisplayed: 0  [0402]  (hidden comment: ERJ-2GE0R00X)
R17  ValueDisplayed: 0  [0402]  (hidden comment: ERJ-2GE0R00X)
R18  ValueDisplayed: 0  [0402]  (hidden comment: ERJ-2GE0R00X)
R19  ValueDisplayed: 0  [0402]  (hidden comment: ERJ-2GE0R00X)
R20  ValueDisplayed: 0  [0402]  (hidden comment: ERJ-2GE0R00X)
R21  ValueDisplayed: 0  [0402]  (hidden comment: ERJ-2GE0R00X)
R22  ValueDisplayed: 0  [0402]  (hidden comment: ERJ-2GE0R00X)
R23  ValueDisplayed: 0  [0402]  (hidden comment: ERJ-2GE0R00X)
R24  ValueDisplayed: 0  [0402]  (hidden comment: ERJ-2GE0R00X)
R25  ValueDisplayed: 0  [0402]  (hidden comment: ERJ-2GE0R00X)
R26  ValueDisplayed: 0  [0402]  (hidden comment: ERJ-2GE0R00X)
R27  ValueDisplayed: 0  [0402]  (hidden comment: ERJ-2GE0R00X)
S1  1188E-1K2-V-TR  [SW_1188E]  (value not drawn)
U1  TMS320F280025CPNSR  [PN0080A-MFG]  (parts A,B,C,D of 4)

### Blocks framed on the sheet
F28002x Device: C9-C16 C18-C40 J15 L2 L3 R10 R12-R27 U1
Reset Button: C17 R11 S1

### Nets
+3V3: C16.1 C18.1 L2.2 L3.1 R10.2 R11.2
GND: C9.1 C10.2 C11.2 C12.2 C13.2 C14.1 C15.2 C16.2 C17.1 C18.2 C19.2 C20.1 C21.1 C22.1 C23.1 C24.2 C25.2 C26.2 C27.2 C28.2 C29.2 C30.2 C31.2 C32.2 C33.2 C34.2 C35.2 C36.2 C37.2 C38.2 C39.2 C40.2 J15.2 S1.1 S1.2 S1.3 U1.9(VSS) U1.21(VREFLO) U1.25(VSSA) U1.30(VSS) U1.55(VSS) U1.70(VSS)
VDD: C9.2 C10.1 C11.1 C12.1 C13.1 U1.8(VDD) U1.31(VDD) U1.53(VDD) U1.71(VDD)
VDDA: C14.2 C15.1 L2.1 U1.26(VDDA)
VDDIO: C19.1 C20.2 C21.2 C22.2 C23.2 L3.2 U1.7(VDDIO) U1.32(VDDIO) U1.52(VDDIO) U1.72(VDDIO)
ADCINA0/C15: R12.1
ADCINA1: R13.1
ADCINA2/C9: R14.1
ADCINA3/C5: R15.1
ADCINA4/C14: R16.1
ADCINA5/C2: R17.1
ADCINA6: R18.1
ADCINA7/C3: R19.1
ADCINA8/C11: R20.1
ADCINA9/C8: R21.1
ADCINA10/C10: R22.1
ADCINA11/C0: R23.1
ADCINA12/C1: R24.1
ADCINA14/C4: R25.1
ADCINA15/C7: R26.1
ADCINC6: R27.1
GPIO0: U1.63(GPIO0)
GPIO1: U1.62(GPIO1)
GPIO2: U1.61(GPIO2)
GPIO3: U1.60(GPIO3)
GPIO4: U1.59(GPIO4)
GPIO5: U1.74(GPIO5)
GPIO6_FSITXD0: U1.80(GPIO6)
GPIO7_FSITXCLK: U1.68(GPIO7)
GPIO8: U1.58(GPIO8)
GPIO9: U1.75(GPIO9)
GPIO10: U1.76(GPIO10)
GPIO11: U1.37(GPIO11)
GPIO12_FSIRXD0: U1.36(GPIO12)
GPIO13_FSIRXCLK: U1.35(GPIO13)
GPIO14: U1.79(GPIO14)
GPIO15: U1.78(GPIO15)
GPIO16: U1.39(GPIO16)
GPIO17: U1.40(GPIO17)
GPIO18_X2: U1.50(GPIO18/X2)
GPIO19_X1: U1.51(GPIO19/X1)
GPIO22: U1.67(GPIO22)
GPIO23: U1.65(GPIO23)
GPIO24: U1.41(GPIO24)
GPIO25: U1.42(GPIO25)
GPIO26: U1.43(GPIO26)
GPIO27: U1.44(GPIO27)
GPIO28: U1.4(GPIO28)
GPIO29: U1.3(GPIO29)
GPIO30: U1.1(GPIO30)
GPIO31: U1.2(GPIO31)
GPIO32: U1.49(GPIO32)
GPIO33: U1.38(GPIO33)
GPIO34: U1.77(GPIO34)
GPIO35: U1.48(GPIO35/TDI)
GPIO37: U1.46(GPIO37/TDO)
GPIO39: U1.56(GPIO39)
GPIO40: U1.64(GPIO40)
GPIO41_FSIRXD1: U1.66(GPIO41)
GPIO42: U1.57(GPIO42)
GPIO43: U1.54(GPIO43)
GPIO44: U1.69(GPIO44)
GPIO45: U1.73(GPIO45)
GPIO46_FSITXD1: U1.6(GPIO46)
MCU_TCK: U1.45(TCK)
MCU_TMS: R10.1 U1.47(TMS)
XRSn: C17.2 R11.1 S1.4 U1.5(~{XRS})
NetC24_1: C24.1 J15.1 U1.20(VREFHI)
NetC25_1: C25.1 R12.2 U1.19(A0/C15)
NetC26_1: C26.1 R14.2 U1.13(A2/C9)
NetC27_1: C27.1 R16.2 U1.27(A4/C14)
NetC28_1: C28.1 R18.2 U1.10(A6)
NetC29_1: C29.1 R20.2 U1.24(A8/C11)
NetC30_1: C30.1 R22.2 U1.29(A10/C10)
NetC31_1: C31.1 R24.2 U1.22(A12/C1)
NetC32_1: C32.1 R26.2 U1.14(A15/C7)
NetC33_1: C33.1 R13.2 U1.18(A1)
NetC34_1: C34.1 R15.2 U1.12(A3/C5)
NetC35_1: C35.1 R17.2 U1.17(A5/C2)
NetC36_1: C36.1 R19.2 U1.23(A7/C3)
NetC37_1: C37.1 R21.2 U1.28(A9/C8)
NetC38_1: C38.1 R23.2 U1.16(A11/C0)
NetC39_1: C39.1 R25.2 U1.15(A14/C4)
NetC40_1: C40.1 R27.2 U1.11(C6)

Not connected (* = marked no-connect by the designer): U1 33(FLT2)* 34(FLT1)*

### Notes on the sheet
- Place near U1

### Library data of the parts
C9 C18 C19 = CMP-0007318-5: CAP, CERM, 10 uF, 10 V, +/- 20%, X5R, 0603; Manufacturer: MuRata; Polarized: N; Value: 10uF; U/M: EA; Cap_F: 10µF; Value1: Unknown; VDC_V: 10V; TaMin_C: -55°C; TaMax_C: 85°C; SizeArea_mm2: 1.28; SizeAreaWB_mm2: 4.68; SizeX_mm: 1.6; SizeY_mm: 0.8; SizeZ_mm: 1; AEC Category: Q200
C10-C14 C17 C20-C23 = CMP-0006629-2: as C74 on sheet MCU089B_Connectors
C15 C16 = CMP-0007323-5: CAP, CERM, 2.2 uF, 10 V, +/- 10%, X5R, 0603; Manufacturer: MuRata; Polarized: N; Value: 2.2uF; U/M: EA; Cap_F: 2.2µF; Value1: Unknown; VDC_V: 10V; TaMin_C: -55°C; TaMax_C: 85°C; SizeArea_mm2: 1.28; SizeAreaWB_mm2: 4.68; SizeX_mm: 1.6; SizeY_mm: 0.8; SizeZ_mm: 1; AEC Category: Q200
C24 = CMP-0007323-5: CAP, CERM, 2.2 uF, 10 V, +/- 10%, X5R, 0603; Manufacturer: MuRata; Polarized: N; Value: 2.2uF; U/M: EA; Value1: Unknown; VDC_V: 10V; TaMin_C: -55°C; TaMax_C: 85°C; SizeArea_mm2: 1.28; SizeAreaWB_mm2: 4.68; SizeX_mm: 1.6; SizeY_mm: 0.8; SizeZ_mm: 1; AEC Category: Q200
C25-C40 = CMP-0006249-2: CAP, CERM, 220 pF, 50 V, +/- 1%, C0G/NP0, 0402; Manufacturer: TDK; TaMin_C: -55°C; Polarized: N; SizeAreaWB_mm2: 3; Value1: Unknown; U/M: EA; Value: 220pF; TaMax_C: 125°C; SizeZ_mm: 0.6; SizeX_mm: 1; SizeY_mm: 0.5; Value2: 50V; AEC Category: Q200
J15 = CMP-0054794-1: Header, 2.54 mm, 2x1, Gold, TH; Manufacturer: Wurth Elektronik; Green_Lifecycle: Active; Green_REACh: Passed; CNHeader: TRUE; CT: FALSE
L2 = CMP-0003093-1: Ferrite Bead, 60 ohm @ 100 MHz, 3 A, 0805; Manufacturer: Wurth Elektronik; Ztyp@1GHz_Ohm: 95.384; ZTyp@100MHz_Ohm: 60; SizeAreaWB_mm2: 6.75; DCR_ohm: 0.025; Value1: 0.025 ohm; Imax_A: 3A; SizeZ_mm: 1.45; SizeX_mm: 2; SizeY_mm: 1.25; SizeArea_mm2: 2.5
L3 = CMP-0003073-1: Ferrite Bead, 220 ohm @ 100 MHz, 2 A, 0805; Manufacturer: Wurth Elektronik; Ztyp@1GHz_Ohm: 190.289; ZTyp@100MHz_Ohm: 220; SizeAreaWB_mm2: 6.75; DCR_ohm: 0.05; Value1: 0.05 ohm; Value: 220 ohm; Imax_A: 2A; SizeZ_mm: 1.45; SizeX_mm: 2; SizeY_mm: 1.25; SizeArea_mm2: 2.5
R10 R11 = CMP-0026890-5: RES, 2.2 k, 5%, 0.063 W, AEC-Q200 Grade 0, 0402; Manufacturer: Vishay-Dale; Value: 2.2k; Value_Code: 2k20; Power_W: 63mW; Value2: 0.063W; VDC_V: 50V; TempCo: 200 ppm/C; SizeArea_mm2: 0.5; SizeX_mm: 1; SizeZ_mm: 0.6; EIA_Code: E24; AEC Category: Q200; AEC Qualified: Y; AEC Grade: 0
R12-R27 = CMP-0026992-3: RES, 0, 5%, 0.1 W, AEC-Q200 Grade 0, 0402; Manufacturer: Panasonic; Power_W: 100mW; TempCo: 600 ppm/C; Value_Code: 0000; Value: 0; EIA_Code: E24; SizeX_mm: 1; SizeY_mm: 0.5; SizeZ_mm: 0.6; Value2: 0.1W; AEC Qualified: Y; VDC_V: 50V; AEC Category: Q200; SizeAreaWB_mm2: 3
S1 = CMP-0002328-1: Switch, SPST, 0.05 A, 12 VDC, SMD; Manufacturer: Diptronics; SizeAreaWB_mm2: 53.9; SizeArea_mm2: 27.3; SizeX_mm: 7.8; SizeY_mm: 3.5; VDC_V: 12V; PositionCount: 1; CurrentRating_mA: 50A
U1 = CMP-0089804-2: 32-bit MCU with 100 MHz, FPU, TMU, 128-KB flash, CLB 80-LQFP -40 to 125; Manufacturer: Texas Instruments; TJmax_C: +125°C; Number Of Spi Channels: 2; CompType: IC; Max Supply Voltage: 3.63V; Number Of Pwm Channels: 14; AEC Qualified: No; Memory Size: 128KBytes; Interface: I2C,SPI,UART,CAN,LIN,SCI,Other; Min Supply Voltage: 2.8V; SizeZ_mm: 1.6mm; Number Of Adc Channels: 16; Number Of Timers/Counters: 3; Ram Size: 24KBytes; Number Of Cores: 1; Frequency_Fixed: 100MHz; Number Of I/Os: 43; Data Bus Width: 32bits; Standoff Height: 0.05mm; Core Architecture: TMS320C28x; AEC Category: Q200; TaMin_C: -40°C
